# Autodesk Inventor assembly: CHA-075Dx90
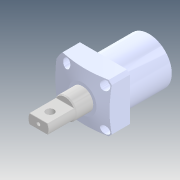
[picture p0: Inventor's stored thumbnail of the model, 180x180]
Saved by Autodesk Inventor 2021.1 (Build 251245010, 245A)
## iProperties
Created: 2018-07
Part Number: CHA-075Dx90
Description: STEP AP214
Document SubType Name: Assembly
Designer: user
Title: CHA-075D(Ë«±Û£©.STEP
Revision Number: ÈÎºÎ
Sending System: SolidWorks 2016
Preprocessor: SwSTEP 2.0
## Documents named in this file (3)
- D:\Vault_2016\Projekty\Clamptek\Hydraulic\CHA\CHA\CHA-075\Inventor\CHA-075Dx90\CHA-075Dx90.iam
- D:\Vault_2016\Projekty\Clamptek\Hydraulic\CHA\CHA\CHA-075\Inventor\CHA-075Dx90\CHA-075±¾Ìå.ipt
- D:\Vault_2016\Projekty\Clamptek\Hydraulic\CHA\CHA\CHA-075\Inventor\CHA-075Dx90\CHA-075D(Ë«±Û£©»îÈû¸Ë.ipt
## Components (2 placed, 2 different names)
1. CHA-075±¾Ìå_1
2. CHA-075D(Ë«±Û£©»îÈû¸Ë_2
